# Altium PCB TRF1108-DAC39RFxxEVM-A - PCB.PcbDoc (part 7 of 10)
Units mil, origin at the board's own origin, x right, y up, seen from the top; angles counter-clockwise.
Board outline 4951.22 x 2726.56 mil, 16 copper layers (Top Layer, L2 GND1, L3 PWR1, L4 GND2, L5 PWR2, L6 GND3, L7 Ctrl Signal 1, L8 GND4, L9 GND5, L10 Ctrl Signal 2, L11 GND6, L12 PWR3, L13 GND7, L14 PWR4, L15 GND8, Bottom Layer), stack 80.2 mil thick; 705 components, 433 nets, 3633 pads, 1678 vias.
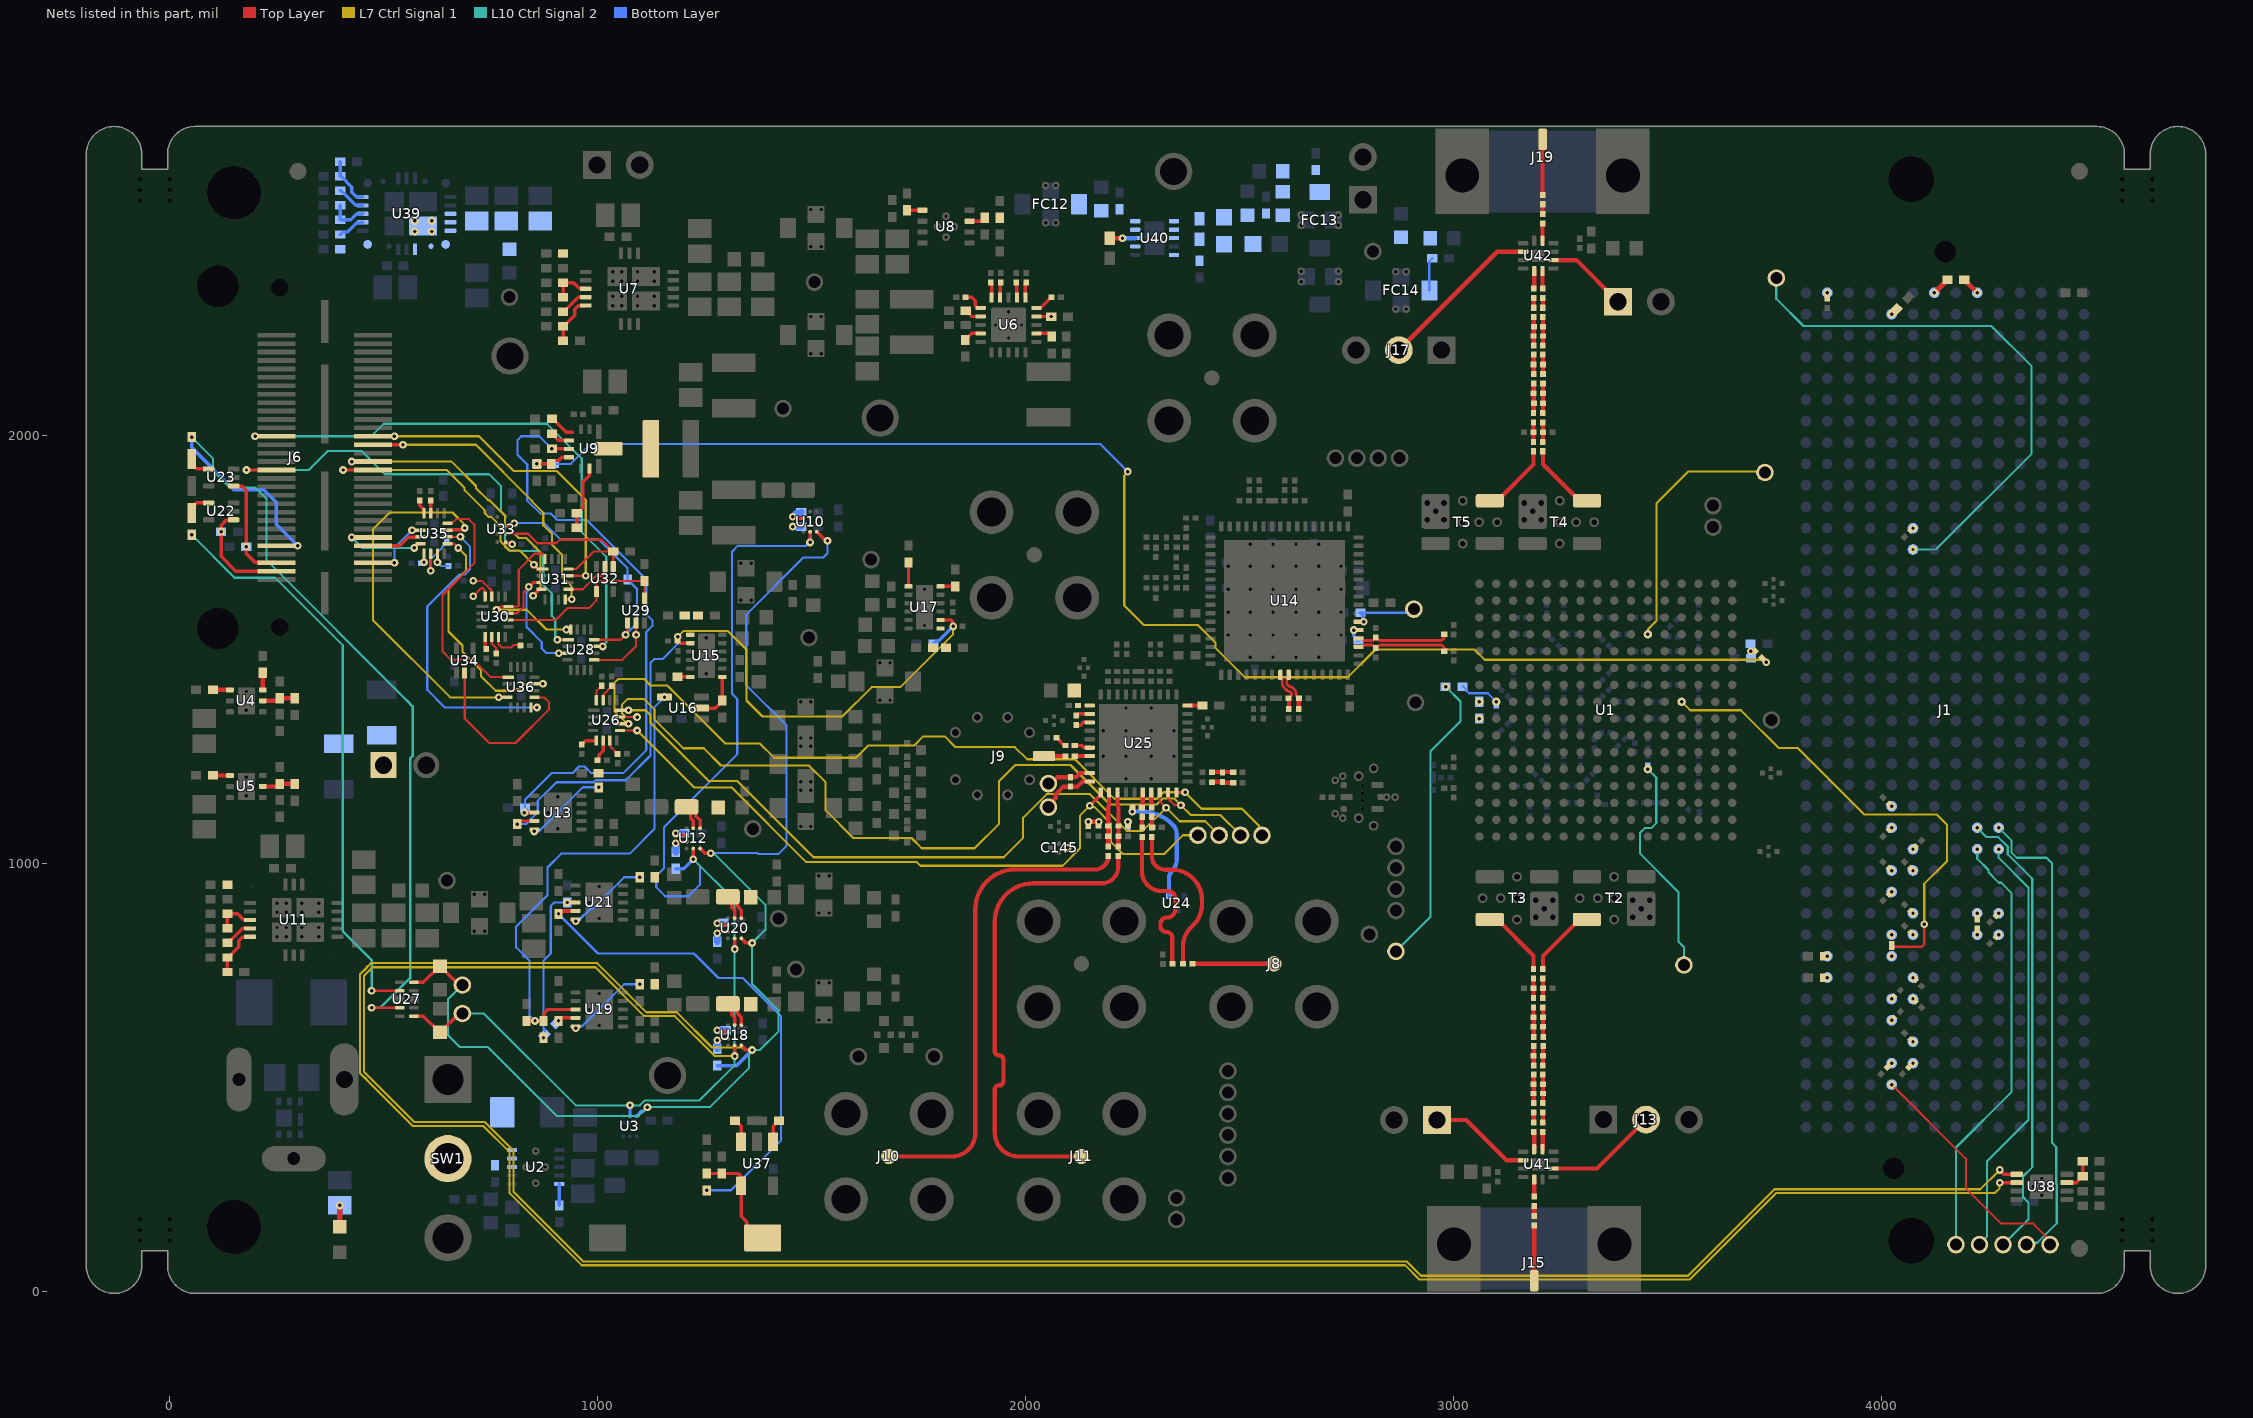
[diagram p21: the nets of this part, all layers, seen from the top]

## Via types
v1: diameter 18, hole 8, Top Layer to Bottom Layer, tented both sides, 1468 vias
v2: diameter 20, hole 10.01, Top Layer to Bottom Layer, 187 vias
v3: diameter 19.68, hole 7.87, Top Layer to Bottom Layer, tented both sides, 16 vias
v4: diameter 19.68, hole 7.87, Top Layer to Bottom Layer, 6 vias
v5: diameter 18/18/18/18/18/18/18/18/18/18/18/18/18/18/18/18 (per signal layer), hole 8, Top Layer to Bottom Layer, tented both sides, 1 vias

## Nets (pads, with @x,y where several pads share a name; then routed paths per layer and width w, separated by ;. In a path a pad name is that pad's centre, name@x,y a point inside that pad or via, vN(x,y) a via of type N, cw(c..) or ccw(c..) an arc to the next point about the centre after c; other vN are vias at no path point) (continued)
NetC139_1: C139.1 U24.2 | length 286.8
  Top Layer w10: v1(2248.91,1120.82) C139.1@2248.91,1130.82
  Bottom Layer w10: v1(2248.91,1120.82) 2271.39,1120.82 cw(c2271.39,1020.82) 2342.1,1091.53 2343.72,1089.91 cw(c2322.34,1068.52) 2352.58,1068.52 2352.58,1009.07 cw(c2313.9,1009.07) 2341.25,981.72 ccw(c2356.67,966.3) 2334.87,966.3 U24.2@2334.87,923.52
NetC139_2: C139.2 C142.1 U25.6 | length 35.7
  Top Layer w10: C142.1@2271.75,1130.82 2271.75,1131.61 2273.43,1133.29 U25.6@2273.43,1165.82
NetC141_1: C141.1 R120.1 | length 383.1
  Top Layer w10: R120.1@2271.75,1061.72 2271.75,980.57 ccw(c2317.23,980.57) 2317.23,935.08 2331.05,935.08 cw(c2331.05,916.5) 2349.63,916.5 2349.63,893.12 cw(c2329.64,893.12) 2329.64,873.13 ccw(c2329.64,858.04) 2314.55,858.04 2314.55,853.66 ccw(c2328.79,853.66) 2328.79,839.42 cw(c2328.79,825.75) 2342.46,825.75 2342.46,813.82 C141.1@2342.5,765
NetC142_2: C142.2 R120.2 | length 25
  Top Layer w10: R120.2@2271.75,1083.77 C142.2@2271.75,1108.77
NetC143_2: C143.2 R119.2 R122.1 | length 52.7
  Top Layer w10: R119.2@2434.81,1189.41 2435.63,1190.23 R122.1@2459.74,1190.23 2459.74,1189.76 2461.03,1188.46 C143.2@2484.81,1188.46 C143.2@2483.86,1189.41
NetC144_2: C144.2 R121.2 R122.2 | length 50
  Top Layer w10: R121.2@2434.81,1213.09 2484.76,1213.09 C144.2@2484.81,1213.14
NetC146_2: C146.2 U25.20 | length 35
  Top Layer w10: U25.20@2377.76,1368.57 C146.2@2412.76,1368.57
NetC147_2: C147.2 C148.1 U25.31
NetC149_1: C149.1 R124.1 | length 383.1
  Top Layer w10: R124.1@2294.8,1061.72 2294.8,1015.97 ccw(c2325.57,1015.97) 2325.57,985.2 2340.83,985.2 cw(c2340.83,914.06) 2411.97,914.06 2411.97,904.89 cw(c2342.46,904.89) 2391.61,855.74 2384.49,848.62 ccw(c2425.52,807.6) 2367.5,807.6 C149.1@2367.5,765
NetC149_2: C149.2 J8.1 | length 190.5
  Top Layer w10: C149.2@2389.55,765 J8.1@2580,765
NetC150_1: C150.1 U25.7 | length 35.7
  Top Layer w10: U25.7@2293.11,1165.82 2293.11,1133.29 2294.8,1131.61 C150.1@2294.8,1130.82
NetC150_2: C150.2 R124.2 R125.2 | length 26.4
  Top Layer w10: R125.2@2295.58,1083.77 2294.8,1084.56 C150.2@2294.8,1108.77 C150.2@2295.58,1107.98
NetC151_1: C151.1 J9.1 | length 50
  Top Layer w10: J9.1@2042.37,1250.46 C151.1@2092.37,1250.46
NetC151_2: C151.2 U25.37 | length 35
  Top Layer w10: C151.2@2114.41,1250.46 U25.37@2149.41,1250.46
NetC152_1: C152.1 R126.2 | length 27.9
  Top Layer w8: R126.2@2072.37,1293.15 2073.15,1293.15 2075.45,1290.85 2075.45,1290.06 2088.07,1277.45 2090.07,1277.45 C152.1@2092.37,1275.15
NetC152_2: C152.2 U25.36 | length 37.1
  Top Layer w8: C152.2@2114.41,1275.15 2130.63,1275.15 2134.7,1271.07 2148.49,1271.07 U25.36@2149.41,1270.15
NetC173_1: C173.1 R176.1 U1.J15 | length 103.2
  Bottom Layer w5: R176.1@3020.44,1412.79 3022.41,1412.79 3029.75,1405.45 3029.75,1403.48 3035.82,1397.41 3079.24,1397.41 v1(3099.18,1377.47) C173.1@3099.18,1368.81
NetC176_2: C176.2 C177.2 C178.2 FB6.1 U39.10 U39.11 U39.12 U39.13 U39.14 U39.15 U39.27
  other v3: 572.24,2475.96 612.6,2475.96 572.24,2501.55 612.6,2501.55
NetC180_2: C180.2 U39.21 | length 64.7
  Bottom Layer w8: C180.2@398.37,2468.99 404.15,2474.78 415.21,2474.78 437.12,2496.69 450.26,2496.69 U39.21@451.18,2497.61
NetC181_1: C181.1 C182.1 FC12.3 U40.7 U40.9 U40.10
NetC183_1: C183.1 R184.1 R185.1 U40.3
NetC183_2: C183.2 C184.1 C185.1 FB7.1 R184.2 U40.1 U40.2
NetC186_1: C186.1 C187.1 FB7.2 FC13.1
NetC188_2: C188.2 U40.8 | length 59.5
  Top Layer w10: C188.2@2196.23,2460.58 v1(2225.93,2460.58)
  Bottom Layer w10: v1(2225.93,2460.58) U40.8@2255.77,2460.58
NetC264_1: C264.1 C274.1 FB10.2 FC14.1 | length 78.1
  Bottom Layer w5: FC14.1@2942.72,2338.36 2942.72,2406.53 C274.1@2949.72,2413.53
NetC265_1: C265.1 R186.1 | length 23.2
  Top Layer w10: R186.1@3187.76,175.87 C265.1@3187.76,199.04
NetC265_2: C265.2 U41.11 | length 40
  Top Layer w10: C265.2@3187.76,221.09 U41.11@3187.76,261.13
NetC266_1: C266.1 R200.1 | length 23.2
  Top Layer w10: R200.1@3208.23,394.5 C266.1@3208.23,417.67
NetC266_2: C266.2 C270.2 C271.2 L4.2 | length 66.5
  Top Layer w10: C266.2@3208.23,439.72 3208.43,439.91 C271.2@3208.43,461.9 ; L4.2@3208.23,506.09 3208.43,505.89 3208.43,462.1 C271.2@3208.63,462.1
NetC267_1: C267.1 C268.1 L5.1 R202.2 | length 68.9
  Top Layer w10: R202.2@3186.18,663.29 3186.38,663.09 3186.38,640.71 C267.1@3186.58,640.51 C268.1@3186.58,617.73 L5.1@3186.58,594.56
NetC267_2: C267.2 C268.2 L3.1 R197.2 | length 68.9
  Top Layer w10: R197.2@3208.23,663.29 3208.43,663.09 3208.43,640.71 C267.2@3208.63,640.51 C268.2@3208.63,617.73 L3.1@3208.63,594.56
NetC269_1: C269.1 L5.2 L6.1 | length 46.1
  Top Layer w10: L5.2@3186.58,573.3 C269.1@3186.58,550.12 3186.78,549.93 3186.78,527.54 L6.1@3186.97,527.35
NetC269_2: C269.2 L3.2 L4.1 | length 46.1
  Top Layer w10: L4.1@3208.23,527.35 3208.43,527.54 3208.43,549.93 C269.2@3208.63,550.12 L3.2@3208.63,573.3
NetC270_1: C270.1 C271.1 C273.2 L6.2 | length 67.7
  Top Layer w10: C273.2@3186.77,439.91 C273.2@3186.97,439.72 3186.58,439.72 C271.1@3186.58,462.1 C270.1@3186.58,483.7 3186.58,506.09 L6.2@3186.97,506.09 L6.2@3186.77,505.89
NetC272_1: C272.1 C281.2 L7.1 | length 45.7
  Top Layer w10: L7.1@3208.23,2188.23 3208.43,2188.03 3208.43,2165.65 C281.2@3208.63,2165.45 C272.1@3208.63,2142.67
NetC272_2: C272.2 C280.2 L8.2 R247.2 | length 68.5
  Top Layer w10: R247.2@3208.23,2052.29 L8.2@3208.23,2075.07 3208.43,2075.26 3208.43,2097.65 C280.2@3208.63,2097.84 C272.2@3208.63,2120.62
NetC273_1: C273.1 R236.1 | length 23.2
  Top Layer w10: R236.1@3186.97,394.5 C273.1@3186.97,417.67
NetC278_1: C278.1 R187.1 | length 23.2
  Top Layer w10: C278.1@3207.44,2516.53 R187.1@3207.44,2539.71
NetC278_2: C278.2 U42.11 | length 40
  Top Layer w10: U42.11@3207.44,2454.45 C278.2@3207.44,2494.49
NetC279_1: C279.1 R250.1 | length 23.2
  Top Layer w10: C279.1@3208.23,2297.91 R250.1@3208.23,2321.08
NetC279_2: C279.2 C282.2 L7.2 L9.2 | length 66.7
  Top Layer w10: L7.2@3208.23,2209.49 3208.43,2209.69 3208.43,2231.68 C282.2@3208.63,2231.88 3208.43,2232.07 3208.43,2253.28 L9.2@3208.23,2253.47 C279.2@3208.23,2275.86
NetC280_1: C280.1 C283.2 L8.1 R252.2 | length 68.8
  Top Layer w10: R252.2@3186.18,2052.29 3186.58,2052.68 3186.58,2074.67 L8.1@3186.97,2075.07 3186.78,2075.26 3186.78,2097.65 C280.1@3186.58,2097.84 C283.2@3186.58,2120.62
NetC281_1: C281.1 C283.1 L10.1 | length 45.7
  Top Layer w10: C283.1@3186.58,2142.67 C281.1@3186.58,2165.45 3186.78,2165.65 3186.78,2188.03 L10.1@3186.97,2188.23
NetC282_1: C282.1 C286.2 L9.1 L10.2 | length 66.5
  Top Layer w10: L10.2@3186.97,2209.49 3186.77,2209.69 3186.77,2231.68 3186.77,2253.28 L9.1@3186.97,2253.47 C286.2@3186.97,2275.86
NetC286_1: C286.1 R255.1 | length 23.2
  Top Layer w10: C286.1@3186.97,2297.91 R255.1@3186.97,2321.08
NetD3_2: D3.2 R5.2 | length 50
  Top Layer w12: D3.2@397.23,150.63 v1(397.23,200.63)
NetF1_2: F1.2 R2.2 SW1.2 U2.3 U2.4 U2.5
NetFB3_1: FB3.1 R57.1 U12.D1 U12.D2 | length 124.1
  Top Layer w8: U12.D2@1223.33,1081.85 1223.33,1099.14 1216.72,1105.75 1216.72,1122.71 R57.1@1207.58,1131.85 1215.29,1131.85 1229.25,1117.89 1229.25,1110.18 1239.08,1100.35 U12.D1@1239.08,1081.85
NetFB4_1: FB4.1 R96.1 U18.D1 U18.D2 | length 124.1
  Top Layer w8: R96.1@1313.22,662.71 1313.22,645.75 1319.83,639.14 U18.D2@1319.83,621.85 ; R96.1@1314.27,662.71 1305.13,671.85 1312.84,671.85 R96.1@1326.8,657.89 ; R96.1@1325.75,657.89 1325.75,650.18 1335.57,640.35 U18.D1@1335.57,621.85
NetFB5_1: FB5.1 R105.1 U20.D1 U20.D2 | length 124.1
  Top Layer w8: U20.D2@1319.83,871.85 1319.83,889.14 1313.22,895.75 1313.22,912.71 R105.1@1304.08,921.85 1311.79,921.85 1325.75,907.89 1325.75,900.18 1335.57,890.35 U20.D1@1335.57,871.85
NetJ1_C26: J1.C26 PP42.1 | length 1112.1
  L10 Ctrl Signal 2 w5: v1(4272.81,1083.06) 4303.21,1052.66 4303.21,1024.94 4315.24,1012.91 4384.76,1012.91 4397.67,1000 4397.67,346.77 4407.62,336.82 4407.62,251.38 4408.56,250.43 4408.56,159.09 4363.09,113.62 4342.74,113.62 PP42.1@4338.12,109
NetJ1_C27: J1.C27 PP44.1 | length 1000.3
  L10 Ctrl Signal 2 w5: PP44.1@4228.12,109 4228.12,109.85 4245.42,127.15 4245.42,303.42 4342.51,400.51 4342.51,942.85 4272.81,1012.56 v1(4272.81,1033.06)
NetJ1_D26: J1.D26 PP43.1 | length 1082.8
  L10 Ctrl Signal 2 w5: v1(4222.81,1083.06) 4244.65,1061.21 4272.37,1061.21 4294.21,1039.37 4294.21,1021.21 4351.51,963.9 4351.51,290.26 4329.69,268.43 4329.69,220.32 4342.8,207.21 4342.8,168.68 PP43.1@4283.12,109
NetJ1_D27: J1.D27 PP45.1 | length 1014.4
  L10 Ctrl Signal 2 w5: PP45.1@4173.12,109 4173.12,336.1 4303.21,466.19 4303.21,930.37 4278.9,954.68 4273.46,954.68 4249.15,979 4249.15,984.43 4222.81,1010.77 v1(4222.81,1033.06)
NetJ1_G12: J1.G12 R209.2
  other v1: 4072.81,1783.06
NetJ1_G13: J1.G13 PP48.1 | length 1284.4
  L10 Ctrl Signal 2 w5: PP48.1@3753.4,2367.25 3753.4,2318.83 3816.98,2255.26 4255.74,2255.26 4350,2161 4350,1956.94 4126.12,1733.06 v1(4072.81,1733.06)
NetJ1_G27: J1.G27 R216.2
  other v1: 4072.81,1033.06
NetJ1_G28: J1.G28 R218.2
  other v1: 4072.81,983.06
NetJ1_G30: J1.G30 R220.2
  other v1: 4072.81,883.06
NetJ1_G31: J1.G31 R222.2
  other v1: 4072.81,833.06
NetJ1_G33: J1.G33 R224.2
  other v1: 4072.81,733.06
NetJ1_G34: J1.G34 R226.2
  other v1: 4072.81,683.06
NetJ1_G36: J1.G36 R228.2
  other v1: 4072.81,583.06
NetJ1_G37: J1.G37 R230.2 | length 13.3
  Top Layer w8: R230.2@4063.4,523.65 v1(4072.81,533.06)
NetJ1_H25: J1.H25 R211.2
  other v1: 4022.81,1133.06
NetJ1_H26: J1.H26 R212.2
  other v1: 4022.81,1083.06
NetJ1_H28: J1.H28 R217.2
  other v1: 4022.81,983.06
NetJ1_H29: J1.H29 R219.2
  other v1: 4022.81,933.06
NetJ1_H31: J1.H31 R221.2
  other v1: 4022.81,833.06
NetJ1_H32: J1.H32 R223.2
  other v1: 4022.81,783.06
NetJ1_H34: J1.H34 R225.2
  other v1: 4022.83,683.06
NetJ1_H35: J1.H35 R227.2
  other v1: 4022.81,633.06
NetJ1_H37: J1.H37 R229.2 | length 13.3
  Top Layer w8: R229.2@4013.4,523.65 v1(4022.81,533.06)
NetJ1_H38: J1.H38 PP49.1 | length 571.1
  Top Layer w5: v1(4022.81,483.06) 4196.23,309.64 4196.23,241.19 4279.24,158.19 4353.75,158.19 4383.23,128.71 4383.23,128.63 4393.12,118.74 PP49.1@4393.12,109
NetJ1_L1: J1.L1 R231.2 | length 14
  Top Layer w12: R231.2@3872.81,2319.08 v1(3872.81,2333.06)
NetJ1_L32: J1.L32 R232.2
  other v1: 3872.81,783.06
NetJ1_L33: J1.L33 R233.2
  other v1: 3872.81,733.06
NetJ3_1: J3.1 R6.1 R7.1
NetJ6_4: J6.4@249.41,1682.56 R111.2 U22.1 | length 251.2
  Top Layer w8: U22.1@149.41,1802.56 148.37,1801.52 131.52,1801.52 120,1790 v1(120,1775) 120,1717.21 154.65,1682.56 J6.4@249.41,1682.56
NetJ10_1: J10.1 R133.1 | length 1138
  Top Layer w10: J10.1@1680,315 1826.95,315 ccw(c1826.95,370.33) 1882.28,370.33 1882.28,892.81 cw(c1974.82,892.81) 1974.82,985.35 2161.22,985.35 ccw(c2161.22,1017.14) R133.1@2193.01,1017.14
NetJ11_1: J11.1 R136.1 | length 1136.9
  Top Layer w10: J11.1@2130,315 1983.05,315 cw(c1983.05,370.33) 1927.72,370.33 1927.72,471.18 cw(c1937.72,471.18) 1937.72,481.18 ccw(c1937.72,491.27) 1947.81,491.27 1947.81,541.09 ccw(c1937.72,541.09) 1937.72,551.18 cw(c1937.72,561.18) 1927.72,561.18 1927.72,864.03 cw(c2016.78,864.03) 2016.78,953.08 2176.99,953.08 ccw(c2176.99,992.15) 2216.06,992.15 R136.1@2216.06,1017.14
NetJ15_1: J15.1 R186.2 | length 129
  Top Layer w10: J15.1@3187.76,24.83 R186.2@3187.76,153.82
NetJ19_1: J19.1 R187.2 | length 129.8
  Top Layer w10: R187.2@3207.44,2561.76 J19.1@3207.44,2691.53
NetL1_1: L1.1 U9.10
NetPP10_1: PP10.1 R83.2 U14.6 | length 152.4
  Bottom Layer w5: R83.2@2781.6,1585.21 2781.81,1585.21 2888.22,1585.21 2896.77,1593.76 PP10.1@2906.52,1593.76
  Bottom Layer w8: R83.2@2781.81,1585.21 2787.66,1579.36 2787.66,1566.39 v1(2789.57,1564.48)
NetPP17_1: PP17.1 R128.2 U25.40 | length 128.8
  Top Layer w10: PP17.1@2052.92,1131.09 2052.92,1135.25 2070.11,1152.45 2070.11,1160.82 2088.34,1179.05 2120.74,1179.05 2133.11,1191.41 U25.40@2149.41,1191.41
NetPP18_1: PP18.1 R128.1 U25.39 | length 106.9
  Top Layer w10: PP18.1@2052.92,1186.09 2059.27,1186.09 2074.27,1201.09 R128.1@2104.41,1201.09 2105.17,1201.85 2118.26,1201.85 2127.5,1211.09 U25.39@2149.41,1211.09
NetPP19_1: PP19.1 U25.8 U26.12 | length 1768.3
  Top Layer w5: U26.12@1051.94,1357.41 v1(1071.94,1357.41) ; U25.8@2312.8,1165.82 2312.8,1145.1 v1(2327.85,1130.05)
  L7 Ctrl Signal 1 w5: v1(1071.94,1357.41) 1111.98,1357.41 1123.26,1346.14 1123.26,1328.08 1170.33,1281.01 1259.04,1192.29 1325.99,1192.29 1504.12,1014.16 1948.62,1014.16 1993.81,1059.35 1993.81,1106.64 2048.77,1161.59 2150.18,1161.59 2236.08,1075.7 2273.5,1075.7 v1(2327.85,1130.05) 2359.69,1098.21 2419.18,1098.21 PP19.1@2451.89,1065.5
NetPP20_1: PP20.1 U25.9 U26.11 | length 2015.3
  Top Layer w5: U26.11@1051.94,1341.67 v1(1091.94,1341.67) ; U25.9@2332.48,1165.82 2332.48,1151.41 2348.08,1135.82 v1(2362.48,1135.82)
  L7 Ctrl Signal 1 w5: v1(1091.94,1341.67) 1065.77,1341.67 1056.44,1350.99 1056.44,1370.01 1070.46,1384.03 1107.8,1384.03 1132.26,1359.57 1132.26,1336.46 1199.99,1268.72 1247.91,1268.72 1288.04,1228.6 1493.12,1228.6 1532.42,1189.3 1532.42,1123.93 1597.13,1059.21 1733.08,1059.21 1757.07,1035.23 1880.17,1035.23 1937.68,1092.74 1937.68,1192.29 1975.11,1229.72 2104.35,1229.72 2196.69,1137.39 2306.02,1137.39 2319.95,1151.32 2346.98,1151.32 v1(2362.48,1135.82) 2385.3,1113 2454.39,1113 PP20.1@2501.89,1065.5
NetPP21_1: PP21.1 U25.1 U26.9 | length 1713.1
  Top Layer w5: U26.9@1051.94,1310.17 v1(1091.94,1310.17)
  Top Layer w8: v1(2149.41,1134.29) 2173.13,1158.01 2174.08,1158.01 2175,1158.93 U25.1@2175,1165.82
  L7 Ctrl Signal 1 w5: v1(1091.94,1310.17) 1225.19,1176.92 1312.95,1176.92 1487.06,1002.81 1745.7,1002.81 1754.23,994.27 2086.08,994.27 2126.52,1034.71 2126.52,1111.4 v1(2149.41,1134.29) ; v1@2151.9,1131.81 2159.67,1131.81 2198.65,1092.82 2198.65,1049.95 2227.26,1021.34 2322.92,1021.34 2367.08,1065.5 PP21.1@2401.89,1065.5
NetPP22_1: PP22.1 U25.10 U26.10 | length 1887
  Top Layer w5: U26.10@1051.94,1325.92 v1(1071.94,1325.92) ; U25.10@2352.17,1165.82 v1(2372.17,1165.82)
  L7 Ctrl Signal 1 w5: v1(1071.94,1325.92) 1068.79,1325.92 1039.1,1355.6 1039.1,1400.62 1038.98,1400.74 1038.98,1421.75 1047.64,1430.41 1108.39,1430.41 1123.26,1415.54 1162.18,1415.54 1297.75,1279.97 1378.82,1279.97 1412.35,1246.44 1603.23,1246.44 1632.14,1275.35 1739.78,1275.35 1760.88,1296.45 1810.92,1296.45 1835.96,1271.41 1974.64,1271.41 2003.12,1242.93 2114.85,1242.93 2207.07,1150.71 2306.62,1150.71 2321.72,1165.82 v1(2372.17,1165.82) 2410.63,1127.36 2505.03,1127.36 2545.01,1087.39 2545.01,1072.39 PP22.1@2551.89,1065.5 ; PP22.1@2554.75,1072.39 PP22.1@2560.01,1072.39
NetPP39_1: PP39.1 R175.2 U1.E6 | length 541.8
  L10 Ctrl Signal 2 w5: v1(3453.51,1219.99) 3473.11,1200.39 3473.11,1093.76 3461.54,1082.2 3446.17,1082.2 3434.61,1070.63 3434.61,1033.06 3434.61,1023.09 3524.6,933.1 3524.6,817.15 3537.64,804.11 PP39.1@3537.64,762.6
  Bottom Layer w5: v1(3453.51,1219.99) R175.2@3453.51,1228.65
NetPP40_1: PP40.1 U1.N6 | length 599.7
  L7 Ctrl Signal 1 w5: v1(3453.51,1534.95) 3454.43,1535.88 3454.43,1547.36 3473.28,1566.2 3473.28,1840.61 3548.03,1915.36 3724.53,1915.36 cw(c3724.53,1913.06) PP40.1@3726.83,1913.06
NetPP41_1: PP41.1 R176.2 | length 695.1
  L10 Ctrl Signal 2 w5: PP41.1@2864.85,794.47 2945.89,875.51 2945.89,1262.34 3015.7,1332.15 3015.7,1378.16 v1(2981.07,1412.79)
NetR3_2: R3.2 U2.10 | length 50
  Bottom Layer w9: R3.2@910.24,200.95 U2.10@910.24,250.95
NetR9_1: R9.1 U4.4 | length 40
  Top Layer w10: R9.1@100.83,1405.2 U4.4@140.83,1405.2
NetR10_1: R10.1 R13.2 U4.2 | length 78.4
  Top Layer w10: U4.2@217.6,1379.61 251.7,1379.61 ccw(c251.7,1385.51) R13.2@257.6,1385.51 R10.1@292.6,1385.51
NetR11_1: R11.1 U5.4 | length 40
  Top Layer w10: R11.1@100.83,1205.2 U5.4@140.83,1205.2
NetR12_1: R12.1 R14.2 U5.2 | length 78.4
  Top Layer w10: U5.2@217.6,1179.61 251.7,1179.61 ccw(c251.7,1185.51) R14.2@257.6,1185.51 R12.1@292.6,1185.51
NetR16_1: R16.1 U6.12 | length 42
  Top Layer w8: R16.1@1859.71,2291.36 1861.68,2291.36 1867.52,2285.52 1867.52,2283.55 1873.71,2277.36 U6.12@1894.71,2277.36
NetR17_1: R17.1 U6.14 | length 43.2
  Top Layer w8: R17.1@1858.91,2222.99 1858.91,2224.96 1864.75,2230.8 1866.72,2230.8 1873.91,2237.99 U6.14@1894.71,2237.99
NetR18_1: R18.1 U6.2 | length 39.5
  Top Layer w8: U6.2@2024.63,2237.99 2054.59,2237.99 2060.43,2232.15 R18.1@2060.43,2230.83
NetR19_2: R19.2 U6.11 | length 51.2
  Top Layer w8: R19.2@1860.5,2322.05 1874,2322.05 1881.52,2314.53 1881.52,2303.15 1886.9,2297.77 1893.99,2297.77 U6.11@1894.71,2297.05
NetR21_2: R21.2 U6.10 | length 35.8
  Top Layer w8: R21.2@1918.3,2356.65 1920.3,2354.65 U6.10@1920.3,2321.65
NetR22_2: R22.2 U6.9 | length 35.8
  Top Layer w8: U6.9@1939.99,2321.65 1939.99,2354.65 R22.2@1941.99,2356.65
NetR23_2: R23.2 U6.7 | length 35.8
  Top Layer w8: R23.2@1977.36,2356.65 1979.36,2354.65 U6.7@1979.36,2321.65
NetR24_2: R24.2 U6.6 | length 35.8
  Top Layer w8: U6.6@1999.04,2321.65 1999.04,2354.65 R24.2@2001.04,2356.65
NetR25_1: R25.1 R28.2 U7.24 | length 115.2
  Top Layer w8: R28.2@919.01,2220.63 R25.1@919.01,2254.63 920.98,2254.63 926.82,2260.47 926.82,2260.65 946.57,2280.39 946.57,2294.54 954.15,2302.11 970.98,2302.11 U7.24@971.82,2302.95
NetR26_2: R26.2 U6.5 | length 45.8
  Top Layer w8: U6.5@2024.63,2297.05 2025.36,2297.77 2035.36,2297.77 2056.55,2318.96 2056.55,2319.75 2058.84,2322.05 R26.2@2059.63,2322.05
NetR27_1: R27.1 R30.2 U7.22 | length 92.7
  Top Layer w8: R30.2@919.01,2322.63 R27.1@919.01,2356.63 943.33,2356.63 956.71,2343.24 970.9,2343.24 U7.22@971.82,2342.32
NetR29_2: R29.2 U7.23 | length 66.9
  Top Layer w8: R29.2@919.01,2288.63 920.98,2288.63 954.99,2322.64 U7.23@971.82,2322.64
NetR31_1: R31.1 U8.5 | length 36
  Top Layer w8: R31.1@1722.49,2525.79 U8.5@1758.49,2525.79
NetR32_1: R32.1 R33.2 U8.3 | length 40.3
  Top Layer w8: U8.3@1868.73,2500.2 1894,2500.2 1894.26,2500.46 1898.68,2500.46 1904.53,2506.3 R32.1@1904.53,2508.27
NetR35_1: R35.1 R39.2 U9.7 | length 152.4
  Top Layer w8: R39.2@950.96,1783.43 R35.1@950.96,1817.43 952.93,1817.43 958.77,1823.27 958.77,1825.24 965.59,1832.06 965.59,1891.3 979.72,1905.43 979.72,1921.5 U9.7@980.64,1922.42
NetR37_2: R37.2 U10.B3 | length 38.7
  Top Layer w8: v1@1461.69,1790.31 U10.B3@1480.35,1790.31
  Bottom Layer w16: v1(1455.35,1786.68) R37.2@1475.35,1786.68
NetR38_2: R38.2 U10.C3 | length 43.2
  Top Layer w8: v1@1461.69,1806.05 U10.C3@1480.35,1806.05
  Bottom Layer w15: v1(1455.35,1809.68) 1464.01,1818.34 1473.01,1818.34 R38.2@1475.35,1820.68
NetR40_1: R40.1 R43.1 R44.2 U9.4 | length 81.3
  Top Layer w8: v1(857.91,1933.19) 890.94,1933.19 898.75,1941 908.29,1941 915.79,1948.5 U9.4@932.91,1948.5
NetR41_2: R41.2 U9.2 | length 47.5
  Top Layer w8: R41.2@892.91,2003.19 894.87,2003.19 900.72,1997.35 900.72,1995.38 908.22,1987.87 U9.2@932.91,1987.87
NetR42_2: R42.2 U9.1 | length 60.8
  Top Layer w8: R42.2@892.91,2038.19 894.87,2038.19 926,2007.06 U9.1@940.78,2007.06
NetR43_2: R43.2 R46.1 | length 3332.4
  Top Layer w4: R46.1@3719.63,1479.99 v1(3729.64,1469.98)
  L7 Ctrl Signal 1 w5: v1(2238.4,1915.17) 2238.4,1914.14 2230,1905.74 2230,1602.38 2275.59,1556.8 2401.89,1556.8 2442.88,1515.81 2442.88,1503.68 2511.83,1434.74 2752.28,1434.74 2816.91,1499.36 3048.16,1499.36 3072.03,1475.48 3720.62,1475.48 3726.12,1469.98 v1(3729.64,1469.98)
  Bottom Layer w5: R43.2@897.28,1933.19 937.19,1933.19 983.45,1979.44 2174.13,1979.44 v1(2238.4,1915.17)
NetR45_1: R45.1 R46.2 R47.2 | length 10
  Top Layer w5: v1(3694.04,1495.58) R46.2@3704.04,1495.58
NetR49_1: R49.1 R51.2 U11.24 | length 115.2
  Top Layer w8: R51.2@134.77,745.98 R49.1@134.77,779.98 136.74,779.98 161.54,804.79 161.54,819.1 169.91,827.47 186.74,827.47 U11.24@187.58,828.31
NetR50_1: R50.1 R53.2 U11.22 | length 92.7
  Top Layer w8: R53.2@134.77,847.98 R50.1@134.77,881.98 159.09,881.98 172.48,868.6 186.66,868.6 U11.22@187.58,867.68
NetR52_2: R52.2 U11.23 | length 66.9
  Top Layer w8: R52.2@134.77,813.98 136.74,813.98 170.75,847.99 U11.23@187.58,847.99
NetR54_2: R54.2 U12.B3 | length 38.7
  Top Layer w8: v1@1188.91,1050.35 U12.B3@1207.58,1050.35
  Bottom Layer w16: R54.2@1182.58,1026.73 v1(1182.58,1046.73)
NetR55_2: R55.2 U12.C3 | length 38.7
  Top Layer w8: v1@1188.91,1066.1 U12.C3@1207.58,1066.1
  Bottom Layer w16: v1(1182.58,1069.73) R55.2@1202.58,1069.73
NetR59_1: R59.1 R60.2 U13.5 | length 193
  Bottom Layer w5: v1(851.87,1074.37) 862.09,1074.37 965.24,1177.52 v1(1002.11,1177.52)
NetR82_2: R82.2 U14.5 | length 30.3
  Bottom Layer w8: v1(2765.95,1544.8) 2766.54,1544.21 2766.54,1531.68 2769.89,1528.33 2769.89,1526.36 2775.73,1520.52 R82.2@2777.7,1520.52
NetR84_1: R84.1 U15.1 U16.2 | length 112.7
  Top Layer w8: U16.2@1242.59,1362.69 1274.18,1362.69 1283.56,1372.07 1285.52,1372.07 1291.37,1377.91 R84.1@1291.37,1379.88 U15.1@1291.37,1435.51
NetR85_1: R85.1 R87.2 U15.7
NetR86_2: R86.2 U15.12 | length 30
  Top Layer w8: R86.2@1186.56,1435.51 U15.12@1216.56,1435.51
NetR88_1: R88.1 U17.1 | length 55.6
  Top Layer w8: U17.1@1725.98,1647.11 R88.1@1725.98,1702.74
NetR90_1: R90.1 R92.2 U17.7
NetR91_2: R91.2 U17.12 | length 34
  Top Layer w8: U17.12@1800.79,1647.11 R91.2@1834.79,1647.11
NetR93_2: R93.2 U18.B3 | length 38.7
  Top Layer w8: v1@1285.41,590.35 U18.B3@1304.08,590.35
  Bottom Layer w16: R93.2@1279.08,566.73 v1(1279.08,586.73)
NetR94_2: R94.2 U18.C3 | length 38.7
  Top Layer w8: v1@1285.41,606.1 U18.C3@1304.08,606.1
  Bottom Layer w16: v1(1279.08,609.73) R94.2@1299.08,609.73
NetR98_1: R98.1 R99.2 U19.5 | length 193
  Bottom Layer w5: v1(948.37,614.37) 951.89,614.37 956.11,618.59 962.8,618.59 1061.74,717.52 v1(1098.61,717.52)
NetR101_2: R101.2 U20.B3 | length 38.7
  Top Layer w8: v1@1285.41,840.35 U20.B3@1304.08,840.35
  Bottom Layer w16: R101.2@1279.08,816.73 v1(1279.08,836.73)
NetR102_2: R102.2 U20.C3 | length 35.7
  Top Layer w8: v1@1285.41,856.1 U20.C3@1304.08,856.1
  Bottom Layer w8: v1(1279.08,859.73) 1294.08,859.73 R102.2@1294.08,861.73
NetR103_1: R103.1 R106.1 R107.2 U21.3 | length 379.6
  Top Layer w9: v1(928.37,908.46) U21.3@948.37,908.46
  Bottom Layer w5: v1(873.37,592.32) 876.92,595.87 876.92,610.63 873.37,614.18 873.37,772.69 890.11,789.43 890.11,900.52 898.05,908.46 v1(928.37,908.46)
NetR108_1: R108.1 R109.2 U21.5 | length 193
  Bottom Layer w5: v1(948.37,864.37) 951.89,864.37 956.11,868.59 957.49,868.59 981.93,893.03 987.24,893.03 1061.74,967.52 v1(1098.61,967.52)
NetR112_2: R112.2 R113.1 U22.4 | length 45.9
  Top Layer w8: R112.2@51.14,1830.49 51.14,1832.46 56.98,1838.3 58.95,1838.3 62.58,1841.93 U22.4@91.14,1841.93
NetR115_2: R115.2 R116.1 U23.4 | length 45.9
  Top Layer w8: R115.2@51.14,1932.73 51.14,1930.77 56.98,1924.92 58.95,1924.92 62.58,1921.3 U23.4@91.14,1921.3
NetR123_1: R123.1 U25.32 | length 33.5
  Top Layer w8: R123.1@2118,1345.02 2118,1345.81 2120.3,1348.11 2124.21,1348.11 2124.99,1348.89 U25.32@2149.41,1348.89
NetR123_2: R123.2 U25.33 | length 34
  Top Layer w8: R123.2@2118,1322.98 2128.3,1322.98 2134.53,1329.2 U25.33@2149.41,1329.2
NetR127_1: R127.1 R133.2 R134.2 U25.2 | length 127.7
  Top Layer w10: R133.2@2193.01,1039.18 2193.01,1061.83 ccw(c2191.09,1061.83) R134.2@2192.44,1063.18 R127.1@2192.44,1087.18 2192.44,1131.04 2194.69,1133.29 U25.2@2194.69,1165.82
NetR135_1: R135.1 R136.2 R137.2 U25.3 | length 127.7
  Top Layer w10: U25.3@2214.37,1165.82 2214.37,1133.29 2216.62,1131.04 R135.1@2216.62,1087.18 R137.2@2216.62,1063.18 ccw(c2217.98,1061.83) 2216.06,1061.83 R136.2@2216.06,1039.18
NetR142_2: R142.2 U26.15 | length 42.1
  Top Layer w5: U26.15@1012.57,1381.04 1013.59,1382.05 1013.59,1393.73 1024.03,1404.17 1024.03,1405.21 1029.01,1410.19 1032.8,1413.99 R142.2@1032.8,1414.78
NetR143_2: R143.2 U26.16 | length 39.3
  Top Layer w5: U26.16@996.82,1381.04 996.82,1402.37 1004.64,1410.19 1005.43,1410.19 1009.23,1413.99 R143.2@1009.23,1414.78
NetR144_2: R144.2 U26.5 | length 38.4
  Top Layer w8: R144.2@962.74,1277.34 962.74,1278.13 965.04,1280.43 965.82,1280.43 971.94,1286.55 U26.5@996.82,1286.55
NetR145_1: R145.1 U26.6 | length 51.4
  Top Layer w8: R145.1@999.16,1241.1 999.87,1241.1 1002.17,1243.4 1002.17,1252.44 1012.57,1262.84 U26.6@1012.57,1286.55
NetR146_1: R146.1 R147.2 U26.7 | length 38.8
  Top Layer w5: U26.7@1028.32,1286.55 1029.76,1285.11 1029.76,1272.39 1041.83,1260.31 1041.83,1259.52 1045.63,1255.72 R146.1@1046.42,1255.72
NetR150_1: R150.1 U29.4 U30.10 U32.4 | length 417.6
  Top Layer w5: U30.10@791.94,1568.42 902.11,1568.42 930.24,1596.55 979.82,1596.55 996.93,1613.66 U32.4@996.94,1635.17 ; U32.4@996.94,1635.17 997.52,1635.75 997.52,1652.93 1004.07,1659.48 R150.1@1109.21,1659.48 U29.4@1109.21,1619.48
NetR151_2: R151.2 U28.12 U29.1 U33.B2 | length 612.7
  Top Layer w5: U28.12@991.94,1522.41 1053.21,1522.41 1069.84,1539.05 U29.1@1069.84,1561.21
  Top Layer w8: U33.B2@785.02,1789.73 797.32,1789.73 802.32,1794.73 v1(805.02,1794.73)
  Bottom Layer w5: v1(805.02,1794.73) 874.54,1794.73 913.28,1755.98 1003.05,1755.98 1054.34,1704.69 1069.84,1689.19 R151.2@1069.84,1662.87 1091.79,1640.93 1091.79,1560.99 v1(1065.04,1534.24)
NetR152_2: R152.2 U30.15 | length 67.1
  Top Layer w5: v1(708.95,1659.91) 729.27,1659.91 747.65,1641.54 748.93,1641.54 751.86,1638.61 751.86,1624.24 U30.15@752.57,1623.54
NetR153_2: R153.2 U30.16 | length 51.4
  Top Layer w5: v1(708.95,1624.17) 727.28,1642.49 731.71,1642.49 735.85,1638.35 735.85,1624.51 U30.16@736.82,1623.54
NetR154_1: R154.1 U30.5 | length 29.6
  Top Layer w8: U30.5@736.82,1529.05 736.82,1504.46 739.82,1501.46 R154.1@739.82,1500.68
NetR155_1: R155.1 U30.6 | length 43.6
  Top Layer w5: U30.6@752.57,1529.05 752.57,1513.34 762.82,1503.08 R155.1@762.82,1489.68
NetR156_2: R156.2 U31.12 U32.1 U33.C2 | length 432.8
  Top Layer w5: U33.C2@785.02,1770.04 836.92,1770.04 859.38,1747.58 902.9,1747.58 911.13,1755.81 1008.94,1755.81 1027,1737.75 1027,1735.78 1034.34,1728.44 R156.2@1036.31,1728.44 ; U31.12@931.94,1687.41 950.01,1687.41 991.03,1728.44 R156.2@1036.31,1728.44 ; U32.1@1036.31,1693.44 1036.31,1721.92 R156.2@1036.31,1728.44
NetR157_1: R157.1 R158.2 U30.7 | length 74.7
  Top Layer w5: U30.7@768.32,1529.05 768.32,1511.77 775.62,1504.46 798.55,1504.46 804.39,1510.3 818.09,1510.3 R157.1@819.67,1508.72
NetR160_1: R160.1 U33.D2 | length 17.1
  Top Layer w8: U33.D2@785.02,1750.36 785.31,1750.36 788.4,1747.27 798.11,1747.27 v1(800.02,1745.36)
NetR164_2: R164.2 U35.15 | length 30
  Top Layer w8: U35.15@609.82,1817.67 R164.2@609.82,1847.67
NetR165_1: R165.1 U35.16 | length 34.1
  Top Layer w8: R165.1@584.08,1847.67 584.08,1836.3 594.08,1826.3 U35.16@594.08,1817.67
NetR166_2: R166.2 U35.6 | length 122.2
  Top Layer w5: v1(609.82,1683.18) U35.6@609.82,1723.18
  Bottom Layer w5: v1(609.82,1683.18) 609.82,1710.45 636.4,1737.03 636.4,1738.62 647,1749.21 R166.2@647,1750
NetR167_2: R167.2 U35.5 | length 20
  Top Layer w5: v1(594.08,1703.18) U35.5@594.08,1723.18
NetR168_1: R168.1 R169.2 U35.7 | length 49.2
  Top Layer w5: v1(625.57,1703.18) U35.7@625.57,1723.18
  Bottom Layer w5: v1(625.57,1703.18) 633.79,1694.97 R168.1@651.32,1694.97
NetR171_2: R171.2 R172.1 SW2.1 U37.4 | length 252.9
  Top Layer w8: R172.1@1254.63,275.35 R171.2@1289.63,275.35 1327.72,275.35 1334.83,268.25 U37.4@1334.83,246.59 1334.83,175.57 1348.47,161.93 1348.47,152.46 1375.96,124.96 SW2.1@1385.43,124.96
NetR173_2: R173.2 U37.1 | length 56.9
  Top Layer w8: U37.1@1409.63,348.96 1409.63,385.18 1415.6,391.15 1415.6,393.11 1421.44,398.96 R173.2@1423.41,398.96
NetR174_2: R174.2 U37.3 | length 56.9
  Top Layer w8: R174.2@1321.05,398.96 1323.02,398.96 1328.86,393.11 1328.86,391.15 1334.83,385.18 U37.3@1334.83,348.96
NetR177_1: R177.1 U1.H16
  other v1: 3059.81,1338.1
NetR177_2: R177.2 U1.J16
  other v1: 3059.81,1377.47
NetR178_1: R178.1 R181.2 U39.24 | length 114.2
  Bottom Layer w8: R181.2@398.37,2638.99 R178.1@398.37,2604.99 400.33,2604.99 425.57,2579.75 425.57,2567.23 436.05,2556.75 451.1,2556.75 U39.24@451.18,2556.67
NetR179_2: R179.2 R180.2 U39.22 | length 92.7
  Bottom Layer w8: R180.2@398.37,2536.99 R179.2@398.37,2502.99 422.69,2502.99 436.07,2516.38 450.26,2516.38 U39.22@451.18,2517.3
NetR182_2: R182.2 U39.23 | length 66.9
  Bottom Layer w8: R182.2@398.37,2570.99 400.33,2570.99 434.34,2536.98 U39.23@451.18,2536.98
NetR192_1: R192.1 R196.2 R197.1 | length 45.6
  Top Layer w10: R197.1@3208.23,685.34 R192.1@3208.23,708.12 R196.2@3208.23,730.89
NetR196_1: R196.1 T2.2 | length 168.5
  Top Layer w10: R196.1@3208.23,752.94 3208.23,783.35 3293.47,868.59 T2.2@3310.99,868.59
NetR200_2: R200.2 U41.5 | length 40.8
  Top Layer w10: U41.5@3207.44,331.99 3207.52,332.07 3207.52,371.74 R200.2@3208.23,372.45
NetR201_1: R201.1 T3.2 | length 168.1
  Top Layer w10: T3.2@3084.22,868.59 3101.74,868.59 3186.18,784.14 R201.1@3186.18,752.94
NetR201_2: R201.2 R202.1 R237.2 | length 45.6
  Top Layer w10: R202.1@3186.18,685.34 R201.2@3186.18,730.89
NetR210_1: R210.1 R215.2 U38.3 | length 78.2
  Top Layer w8: U38.3@4432.49,253.88 4454.49,253.88 4461.68,261.07 4461.68,263.04 4469.49,270.85 R210.1@4469.49,303.88
NetR236_2: R236.2 U41.6 | length 40.8
  Top Layer w10: R236.2@3186.97,372.45 3187.76,371.66 U41.6@3187.76,331.99
NetR242_1: R242.1 R246.2 R247.1 | length 45.6
  Top Layer w10: R246.2@3208.23,1984.68 R242.1@3208.23,2007.46 R247.1@3208.23,2030.24
NetR246_1: R246.1 T4.2 | length 168.5
  Top Layer w10: R246.1@3208.23,1962.63 3208.23,1932.22 3293.47,1846.99 T4.2@3310.99,1846.99
NetR250_2: R250.2 U42.6 | length 40.8
  Top Layer w10: U42.6@3207.44,2383.58 3207.44,2343.91 R250.2@3208.23,2343.13
NetR251_1: R251.1 T5.2 | length 168.1
  Top Layer w10: T5.2@3084.22,1846.99 3101.74,1846.99 3186.18,1931.44 R251.1@3186.18,1962.63
NetR251_2: R251.2 R252.1 R256.2 | length 45.6
  Top Layer w10: R251.2@3186.18,1984.68 R256.2@3186.18,2007.46 R252.1@3186.18,2030.24
NetR255_2: R255.2 U42.5 | length 40.8
  Top Layer w10: R255.2@3186.97,2343.13 3187.76,2343.91 U42.5@3187.76,2383.58
NetU28_3: U28.3 U30.11 U31.3 | length 352.7
  Top Layer w5: U30.11@791.94,1584.17 812.26,1584.17 826.95,1598.86 826.95,1633.92 v1(838.95,1645.92) ; v1(908.95,1490.92) U28.3@928.95,1490.92
  Top Layer w8: v1(838.95,1645.92) 848.95,1655.92 U31.3@868.95,1655.92
  Bottom Layer w5: v1(838.95,1645.92) 836.46,1643.43 836.46,1637.55 835.4,1636.49 835.4,1633.54 833.45,1631.59 833.45,1552.3 869.3,1516.44 869.3,1501.81 880.2,1490.92 v1(908.95,1490.92)
NetU28_9: U28.9 U29.2 | length 164.9
  Top Layer w5: U28.9@991.94,1475.17 1057.62,1475.17 1089.53,1507.08 v1(1089.53,1534.15) U29.2@1089.53,1561.21
NetU28_16: U28.16 U30.12 U31.16 | length 418.5
  Top Layer w5: v1(763.49,1592.4) 771,1599.91 U30.12@791.94,1599.91 812.45,1599.91 815.38,1602.84 815.38,1686.12 852.45,1723.19 872.54,1723.19 876.82,1718.91 U31.16@876.82,1711.04 ; v1(926.82,1546.04) U28.16@936.82,1546.04
  L7 Ctrl Signal 1 w5: v1(763.49,1592.4) 833.93,1592.4 880.29,1546.04 v1(926.82,1546.04)
NetU31_9: U31.9 U32.2 | length 116
  Top Layer w5: U31.9@931.94,1640.17 964.95,1640.17 996.53,1671.75 1005.23,1671.75 1005.27,1671.79 1010.81,1671.79 1015.26,1676.24 1015.26,1692.07 U32.2@1016.63,1693.44
NetU34_2: U34.2 U36.9 | length 415.2
  Top Layer w5: U34.2@689.26,1444.4 689.26,1338.28 746.48,1281.06 807.89,1281.06 886.46,1359.63 886.46,1375.86 874.65,1387.67 U36.9@851.94,1387.67
NetU35_9: U35.9 U36.11 | length 569.6
  Top Layer w5: U35.9@649.19,1746.8 649.58,1746.41 664.58,1746.41 v1(674.19,1736.8) ; U36.11@851.94,1419.17 v1(871.94,1419.17)
  L7 Ctrl Signal 1 w5: v1(674.19,1736.8) 691.88,1719.12 691.88,1682.69 651.32,1642.13 651.32,1541.43 684.08,1508.68 684.08,1494.19 727.45,1450.82 727.45,1437.26 761.54,1403.17 805.74,1403.17 809.68,1407.11 819.05,1407.11 831.11,1419.17 v1(871.94,1419.17)
NetU35_10: U35.10 U36.8 | length 733.1
  Top Layer w5: U35.10@649.19,1762.55 v1(679.19,1762.55) ; U36.8@844.07,1364.05 v1(858,1364.05)
  Bottom Layer w5: v1(679.19,1762.55) 701.86,1739.88 701.86,1687.35 689.23,1674.71 676.29,1674.71 601.7,1600.12 601.7,1405.2 642.85,1364.05 v1(858,1364.05)
NetU35_11: U35.11 U36.4 | length 885.1
  Top Layer w5: v1(768.95,1387.67) U36.4@788.95,1387.67
  Top Layer w8: U35.11@649.19,1778.3 660.9,1778.3 662.15,1779.55 v1@682.74,1779.55
  L7 Ctrl Signal 1 w5: v1(689.19,1783.3) 686.71,1785.79 686.71,1793.66 660.82,1819.55 513.96,1819.55 475.4,1780.98 475.4,1567.35 655.08,1387.67 v1(768.95,1387.67)
NetU35_12: U35.12 U36.1 | length 577.3
  Top Layer w5: U35.12@649.19,1794.05 659.19,1794.05 669.19,1804.05 698.54,1804.05 711.8,1790.79 711.8,1701.31 637.2,1626.71 637.2,1495.43 656.84,1475.79 709.42,1475.79 750.29,1434.91 U36.1@790.92,1434.91
PD_AMP1: J13.2 U41.2 | length 263.7
  Top Layer w10: U41.2@3233.03,286.72 3334.75,286.72 J13.2@3449.32,401.28
PD_AMP2: J17.2 U42.2 | length 385.9
  Top Layer w10: J17.2@2871.57,2198.8 3101.62,2428.86 U42.2@3162.17,2428.86
PG-C2M: J1.D1 R204.2 | length 43.7
  Top Layer w12: R204.2@4192.5,2363.06 4194.46,2363.06 4198.31,2359.21 4198.31,2357.56 v1(4222.81,2333.06)
PG-M2C: J1.F1 R204.1 | length 43.7
  Top Layer w12: v1(4122.81,2333.06) 4147.31,2357.56 4147.31,2359.21 4151.16,2363.06 R204.1@4153.13,2363.06
PG_TRF: R189.1 U40.5
PG_VDDL: R95.1 R107.1 U19.4 | length 43.7
  Top Layer w8: v1(908.37,631.69) 908.37,632.94 914.21,638.78 U19.4@948.37,638.78
PRSNT-M2C-L: J1.H2 R208.2 | length 15.6
  Top Layer w12: v1(4022.81,2283.06) R208.2@4033.86,2294.11
PwrGd_3p3Gen: R8.1 U4.3 | length 40
  Top Layer w10: U4.3@217.6,1405.2 R8.1@217.6,1445.2
PwrGd_Analog: R48.1 U11.19
PwrGd_Clock: R20.1 U7.19
PwrGd_Clocking: R15.1 U6.4 | length 35
  Top Layer w8: U6.4@2024.63,2277.36 v1(2059.63,2277.36)
PwrGd_DAC_1p0V: R104.1 R172.2 U21.4 | length 1172.7
  Top Layer w9: v1(908.37,881.69) cw(c925.48,864.58) 925.48,888.78 U21.4@948.37,888.78
  Bottom Layer w5: v1(908.37,881.69) 1000.63,789.43 1224.52,789.43 1230.59,783.36 1282.09,731.86 1338.7,731.86 1428.56,642 1428.56,353.18 1311.37,235.98 v1(1254.63,235.98)
PwrGd_DAC_1p8V: C103.2 C111.2 R56.1 R89.1 U13.4 U15.8 U17.8 | length 1787.5
  Top Layer w5: v1(1186.96,1529.25) 1186.96,1519.25 C103.2@1187.35,1519.25
  Top Layer w8: R56.1@817.71,1098.78 U13.4@851.87,1098.78 ; C103.2@1187.35,1519.25 1192.35,1514.25 U15.8@1216.56,1514.25 ; U17.8@1800.79,1568.37 1825,1568.37 1830,1563.37 1830,1553.76 v1(1830.39,1553.37)
  L7 Ctrl Signal 1 w5: v1(1186.96,1529.25) 1200.19,1542.48 1304.53,1542.48 1347.63,1499.38 1347.63,1380.29 1385.09,1342.83 1571.62,1342.83 1640.34,1411.55 1706.82,1411.55 1830.39,1535.12 v1(1830.39,1553.37)
  Bottom Layer w5: v1(811.87,1091.69) 811.92,1091.75 832.25,1091.75 859.94,1119.43 859.94,1145.74 903.52,1189.33 989.61,1189.33 994.39,1194.11 1065.37,1194.11 1123.26,1252 1123.26,1468.18 1132.11,1477.04 1151.27,1477.04 1186.96,1512.72 v1(1186.96,1529.25)
  Bottom Layer w8: R89.1@1784.37,1512.73 1790.21,1518.57 1795.6,1518.57 v1(1830.39,1553.37)
PwrGd_DAC_Dig: R34.1 R58.1 U9.3 U13.3 | length 1448
  Top Layer w8: v1(828.69,1118.46) U13.3@851.87,1118.46 ; v1(892.91,1968.19) U9.3@932.91,1968.19
  Bottom Layer w5: v1(828.69,1118.46) R58.1@836.1,1125.87 ; R58.1@830,1130 830,1148.57 892.16,1210.73 940.99,1210.73 956.32,1226.05 969.16,1226.05 984.48,1210.73 1059.79,1210.73 1113.38,1264.32 1113.38,1540.46 1127.71,1554.79 1127.71,1567.63 1113.38,1581.97 1113.38,1663.03 974.49,1801.93 905.17,1801.93 889.67,1817.43 865.35,1817.43 835.4,1847.37 835.4,1931.75 812.58,1954.57 812.58,1988.61 821.49,1997.52 863.58,1997.52 v1(892.91,1968.19)
PwrGd_DAC_N1p8V: R97.1 R103.2 U16.4 U19.3 | length 1148.3
  Top Layer w8: R97.1@833.53,631.69 v1(853.53,631.69) R103.2@873.37,631.69 875.13,633.45 875.13,650.82 882.78,658.46 U19.3@948.37,658.46
  Bottom Layer w5: v1(853.53,631.69) 840.35,644.87 840.35,773.01 809.44,803.92 809.44,852.18 882.49,925.23 882.49,990.35 914.6,1022.46 1074.72,1022.46 1132.26,1080 1132.26,1364.57 v1(1155.97,1388.28)
PwrGd_TRF_LDO: R183.1 U39.19
S\Y\N\C\_DAC: R221.1 R223.1 U1.J4 | length 1119.3
  Top Layer w5: R223.1@4022.81,805.1 4093.71,805.1 4099.24,810.63 v1(4099.24,857.75)
  L7 Ctrl Signal 1 w5: v1(3532.25,1377.47) 3552.02,1357.7 3670.49,1357.7 3680,1348.2 3758.52,1269.67 3802.89,1269.67 3958.32,1114.24 4127.85,1114.24 4152.53,1089.57 4152.53,1005.47 4099.24,952.18 v1(4099.24,857.75)
SCL_I2C: PP23.1 R93.1 R148.1 U3.A1 U10.A1 U12.A1 U18.A1 U20.A1 U27.10 U38.6 | length 8508.7
  Top Layer w8: U27.10@570.56,721.7 592.83,721.7 630.58,759.44 R148.1@631.56,759.44 632.55,759.44 676.42,715.57 PP23.1@683.56,715.57 ; U12.A1@1239.08,1034.61 1249.95,1023.73 v1(1264.08,1023.73) ; U18.A1@1335.57,574.61 1346.45,563.73 v1(1360.57,563.73) ; U20.A1@1335.57,824.61 1346.45,813.73 v1(1360.57,813.73) ; U10.A1@1511.85,1774.56 1527.94,1758.47 1529.36,1758.47 1534.14,1753.68 v1(1536.85,1753.68) ; v1(4275.24,253.88) U38.6@4315.24,253.88
  L7 Ctrl Signal 1 w5: v1(1360.57,563.73) 1343.39,563.73 1337.55,569.57 1267.08,569.57 1184.7,651.95 1113.65,651.95 998.88,766.73 470.02,766.73 459.69,756.4 459.69,755.56 444.65,740.52 444.65,509.84 459.69,494.8 459.69,493.95 567.54,386.1 732.86,386.1 794.1,324.86 794.1,229.19 962.45,60.84 2886.33,60.84 2919.67,27.5 3550.87,27.5 3752.96,229.58 4263.7,229.58 4275.24,241.12 v1(4275.24,253.88)
  L10 Ctrl Signal 2 w5: PP23.1@683.56,715.57 650.35,682.36 650.35,598.24 677.78,570.8 742.71,570.8 903.51,410 1095.74,410 v1(1116.09,430.35) 1262.06,430.35 1353.81,522.09 1353.81,554.3 1360.57,561.06 v1(1360.57,563.73) 1378.71,563.73 1422.7,607.72 1422.7,656.22 1360.57,718.34 v1(1360.57,813.73) 1391.57,844.72 1391.57,903.22 1273.55,1021.24 1266.56,1021.24 v1(1264.08,1023.73)
  Bottom Layer w5: v1(1264.08,1023.73) 1373.21,1023.73 1375.57,1021.37 1421.73,1021.37 1441.37,1041 1441.37,1321.76 1346.87,1416.26 1346.87,1580.94 1480.2,1714.27 1526.67,1714.27 1536.85,1724.45 v1(1536.85,1753.68)
  Bottom Layer w8: U3.A1@1091.09,409.47 1101.96,420.35 1106.09,420.35 v1(1116.09,430.35) ; R93.1@1279.08,527.36 1324.2,527.36 v1(1360.57,563.73)
SCL_LOCAL: J1.C30 R205.2
  other v1: 4272.81,883.06
SDA_I2C: PP24.1 R54.1 R149.1 U3.A2 U10.A2 U12.A2 U18.A2 U20.A2 U27.6 U38.5 | length 8259
  Top Layer w8: U27.6@570.56,642.95 592.83,642.95 630.58,605.21 R149.1@631.56,605.21 632.55,605.21 676.42,649.08 PP24.1@683.56,649.08 ; v1(1223.33,1009.61) U12.A2@1223.33,1034.61 ; v1(1319.83,549.61) U18.A2@1319.83,574.61 ; v1(1319.83,799.61) U20.A2@1319.83,824.61 ; v1(1496.1,1749.56) U10.A2@1496.1,1774.56 ; v1(4275.24,283.57) 4285.24,273.57 U38.5@4315.24,273.57
  L7 Ctrl Signal 1 w5: v1(1319.83,549.61) 1273.48,549.61 1180.13,642.95 1109.08,642.95 994.9,757.14 473.99,757.14 453.65,736.79 453.65,513.56 571.52,395.7 735.99,395.7 803.1,328.59 803.1,232.92 966.18,69.84 2890.06,69.84 2923.4,36.5 3547.15,36.5 3749.23,238.58 4230.25,238.58 v1(4275.24,283.57)
  L10 Ctrl Signal 2 w5: PP24.1@683.56,649.08 733.78,649.08 948.4,434.47 v1(1075.34,434.47) 1098.29,434.47 1109.67,445.85 1237.15,445.85 1319.83,528.52 v1(1319.83,549.61) v1(1319.83,799.61) 1319.83,913.11 v1(1223.33,1009.61)
  Bottom Layer w5: v1(1223.33,1009.61) 1238.71,994.23 1238.71,949.54 1212.19,923.02 1157.71,923.02 1136.71,944.01 1136.71,970.39 1154.87,988.54 1154.87,1084.08 1325.89,1255.11 1325.89,1383.7 1314.08,1395.51 1314.08,1728.45 1327.2,1741.57 1486.67,1741.57 1494.66,1749.56 v1(1496.1,1749.56)
  Bottom Layer w8: U3.A2@1075.34,409.47 v1(1075.34,434.47) ; R54.1@1182.58,987.36 1201.08,987.36 v1(1223.33,1009.61)
SDA_LOCAL: J1.C31 R207.2
  other v1: 4272.81,833.06
SDCLKOUT1_n: C76.2 R73.2 U14.4 | length 215.4
  Top Layer w6.5: U14.4@2777.76,1525.11 2781.4,1525.11 cw(c2781.4,1517.27) 2786.95,1522.81 ccw(c2792.49,1528.36) 2792.49,1520.52 2807,1520.52 ccw(c2807,1531.28) 2814.6,1523.66 R73.2@2817.2,1526.27 ; R73.2@2817.76,1527.61 ccw(c2819.66,1527.61) 2818.32,1526.27 ccw(c2832.19,1540.14) 2832.19,1520.52 2968.24,1520.52 ccw(c2968.24,1530.03) 2977.76,1530.03 C76.2@2977.76,1534.95
SDCLKOUT1_p: C75.2 R72.2 U14.3 | length 215.4
  Top Layer w6.5: U14.3@2777.76,1505.43 2781.4,1505.43 ccw(c2781.4,1513.27) 2786.95,1507.72 cw(c2792.49,1502.18) 2792.49,1510.02 2807,1510.02 cw(c2807,1499.25) 2814.61,1506.87 R72.2@2817.2,1504.27 ; R72.2@2817.76,1502.93 cw(c2819.66,1502.93) 2818.32,1504.27 cw(c2832.19,1490.39) 2832.19,1510.02 2968.24,1510.02 cw(c2968.24,1500.5) 2977.76,1500.5 C75.2@2977.76,1495.58
SDCLKOUT3_n: C93.2 R77.2 U14.57 | length 92.8
  Top Layer w6.5: U14.57@2614.37,1440.46 2614.37,1436.82 cw(c2606.53,1436.82) 2612.08,1431.28 ccw(c2617.62,1425.73) 2609.78,1425.73 2609.78,1419.22 2615.38,1413.62 ccw(c2619.26,1417.51) 2619.26,1412.01 cw(c2619.26,1406.52) 2623.14,1410.4 2627.83,1405.72 ; 2627.84,1405.71 cw(c2618.98,1396.87) 2631.49,1396.87 2631.49,1396.09 ccw(c2642.12,1396.09) 2634.61,1388.58 2637.16,1386.02 ccw(c2638.51,1387.37) R77.2@2638.51,1385.46
  Top Layer w10: C93.2@2637.72,1360.46 R77.2@2637.72,1383.56
SDCLKOUT3_p: C92.2 R76.2 U14.56 | length 92.7
  Top Layer w6.5: U14.56@2594.69,1440.46 2594.69,1436.82 ccw(c2602.53,1436.82) 2596.99,1431.28 cw(c2591.44,1425.73) 2599.28,1425.73 2599.28,1419.19 ccw(c2609.72,1419.19) 2602.34,1411.81 2611.03,1403.12 ccw(c2614.91,1407.01) 2614.91,1401.51 cw(c2614.91,1396.02) 2618.8,1399.9 2618.87,1399.83 cw(c2613.73,1394.7) 2620.99,1394.7 cw(c2613.73,1394.7) 2618.87,1389.56 2615.32,1386.02 cw(c2613.98,1387.37) R76.2@2613.98,1385.46
  Top Layer w10: C92.2@2614.77,1360.46 R76.2@2614.77,1383.56
SYSREF_TERM: C145.3 C154.2 C158.2 R127.2 R135.2 | length 66
  Top Layer w10: C158.2@2146.4,1087.18 v1(2146.4,1097.18) v1(2170.4,1097.18) R127.2@2170.4,1087.18 ; R135.2@2238.67,1087.18 v1(2238.67,1097.18)
  Bottom Layer w10: C154.2@2238.67,1085.18 v1(2238.67,1097.18)
  other v1: 2097.41,1035.82
TDI_FMC: J1.D30 R206.2 | length 14
  Top Layer w8: R206.2@4222.81,869.08 v1(4222.81,883.06)
TDO_FMC: J1.D31 R206.1 | length 14
  Top Layer w8: v1(4222.81,833.06) R206.1@4222.81,847.03
TP1_AMP1: J14.1 U41.8 | length 240.5
  Top Layer w10: J14.1@2960.53,400.33 3029.29,400.33 3123.22,306.4 3135.21,306.4 U41.8@3162.17,306.4
TP1_AMP2: J18.1 U42.8 | length 191
  Top Layer w10: U42.8@3233.03,2409.17 3286.64,2409.17 J18.1@3383.82,2311.99
USB_C\S\_DAC: J6.11 U35.4 | length 227.1
  Top Layer w8: v1(425,1761.3) J6.11@475,1761.3 ; v1(571.2,1736.8) 571.2,1739.36 578.39,1746.55 578.39,1746.74 578.45,1746.8 U35.4@586.2,1746.8
  L10 Ctrl Signal 2 w5: v1(425,1761.3) 449.5,1736.8 v1(571.2,1736.8)
USB_CIPO_DAC: J6.9 U35.3 | length 119.9
  Top Layer w8: J6.9@475,1741.61 537.42,1741.61 557.1,1761.3 573.24,1761.3 574.5,1762.55 U35.3@586.2,1762.55
USB_COPI_DAC: J6.5 U35.2 | length 163.1
  Top Layer w5: J6.5@475,1702.24 v1(525,1702.24) ; v1(566.2,1778.3) U35.2@586.2,1778.3
  Bottom Layer w5: v1(525,1702.24) 525,1737.1 v1(566.2,1778.3)
USB_I2C_SCL: R113.2 U27.2 | length 1361.4
  Top Layer w6: v1(471.69,702.01) U27.2@537.69,702.01
  L10 Ctrl Signal 2 w5: v1(51.14,1767.62) 151.52,1667.25 246.43,1667.25 404.24,1509.44
  L10 Ctrl Signal 2 w6: 404.24,1509.44 404.24,841.29 471.69,773.84 v1(471.69,702.01)
USB_I2C_SDA: J6.10 R116.2 U27.4 | length 2149.2
  Top Layer w6: v1(471.69,662.64) U27.4@537.69,662.64
  Top Layer w8: J6.10@248.32,1742.7 J6.10@249.41,1741.61 v1(299.41,1741.61)
  L10 Ctrl Signal 2 w5: v1(51.14,1995.6) 100.83,1945.91 100.83,1917.76 140.76,1877.84 199.79,1877.84 226.46,1851.17 226.46,1708.11 554.22,1380.35
  L10 Ctrl Signal 2 w6: v1(471.69,662.64) 492.93,662.64 561.82,731.54 561.82,1244.75 567.78,1250.7 567.78,1366.79 554.22,1380.35
  Bottom Layer w8: v1(51.14,1995.6) 51.14,1971.43 149.41,1873.16 219.45,1873.16 248.69,1843.92 248.69,1792.34 v1(299.41,1741.61)
USB_I2C_SDAo: J6.6 R114.2 U23.1 | length 258.9
  Top Layer w8: U23.1@149.41,1881.93 150.09,1881.25 169.12,1881.25 173.8,1876.57 ; 175,1875 178.79,1871.21 178.79,1723.79 199.3,1703.28 248.37,1703.28 J6.6@249.41,1702.24
  other v1: 178.79,1740
USB_LMK_C\S\: J6.35 U31.11 | length 775.6
  Top Layer w5: U31.11@931.94,1671.67 v1(971.94,1671.67)
  Top Layer w8: J6.35@475,1997.52 v1(525,1997.52)
  L7 Ctrl Signal 1 w5: v1(525,1997.52) 722.57,1997.52 803.29,1916.8 903.83,1916.8 971.94,1848.7 v1(971.94,1671.67)
USB_LMK_SCK: J6.27 U31.1 | length 659.5
  Top Layer w8: v1(405,1918.78) J6.27@475,1918.78 ; v1(850.92,1697.41) 860.92,1687.41 U31.1@870.92,1687.41
  L7 Ctrl Signal 1 w5: v1(405,1918.78) 647.11,1918.78 688.95,1876.94 688.95,1871.62 736.04,1824.53 736.04,1818.2 744.53,1809.71 750.86,1809.71 772.78,1787.79 772.78,1752.09 794.02,1730.86 817.48,1730.86 v1(850.92,1697.41)
USB_LMK_SDI: J6.29 U31.4 | length 730.2
  Top Layer w8: v1(425,1938.46) J6.29@475,1938.46 ; v1(848.95,1625.17) 861.14,1637.36 861.14,1640.11 861.2,1640.17 U31.4@868.95,1640.17
  L7 Ctrl Signal 1 w5: v1(425,1938.46) 658.57,1938.46 715.69,1881.35 715.69,1876.51 744.12,1848.08 747.18,1848.08 783.41,1811.85 783.41,1791.73 815.29,1759.86 833.08,1759.86 866.22,1726.71 866.22,1704.03 866.42,1703.83 866.42,1642.64 v1(848.95,1625.17)
USB_LMK_SDO: J6.33 U31.8 | length 709.4
  Top Layer w5: U31.8@924.07,1616.55 928,1616.55
  Top Layer w8: J6.33@475,1977.83 v1(545,1977.83) ; 928,1616.55 v1(939.07,1616.55)
  L7 Ctrl Signal 1 w5: v1(545,1977.83) 715.59,1977.83 846.09,1847.33 846.09,1846 872.85,1819.25 872.85,1789.73 893.07,1769.5 893.07,1744.18 916.5,1720.76 916.5,1669.44 939.07,1646.87 v1(939.07,1616.55)
USB_LMX_C\S\: J6.36 U28.11 | length 1344.9
  Top Layer w5: U28.11@991.94,1506.67 v1(1011.94,1506.67)
  Top Layer w8: v1(199.41,1997.52) J6.36@249.41,1997.52
  L10 Ctrl Signal 2 w5: v1(199.41,1997.52) 269.2,1997.52 269.49,1997.81 470.61,1997.81 499.8,2027 881,2027 962.77,1945.23 962.77,1773.58 1019.81,1716.54 1019.81,1516.1 1011.94,1508.23 v1(1011.94,1506.67)
USB_LMX_SCLK: J6.28 U28.1 | length 1197.3
  Top Layer w5: v1@900.92,1522.41 U28.1@930.92,1522.41
  Top Layer w8: v1(179.41,1918.78) J6.28@249.41,1918.78
  L10 Ctrl Signal 2 w5: v1(179.41,1918.78) 324.91,1918.78 369.78,1963.64 448,1963.64 502.63,1909.02 746.24,1909.02 774.41,1880.85 774.41,1822.23 783.41,1813.23 783.41,1740.05 793.6,1729.86 859.55,1729.86 872.89,1716.52 872.89,1650.3 892.57,1630.61 892.57,1577.96 900.92,1569.61 v1@900.92,1522.41
  other v1: 905.92,1522.41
